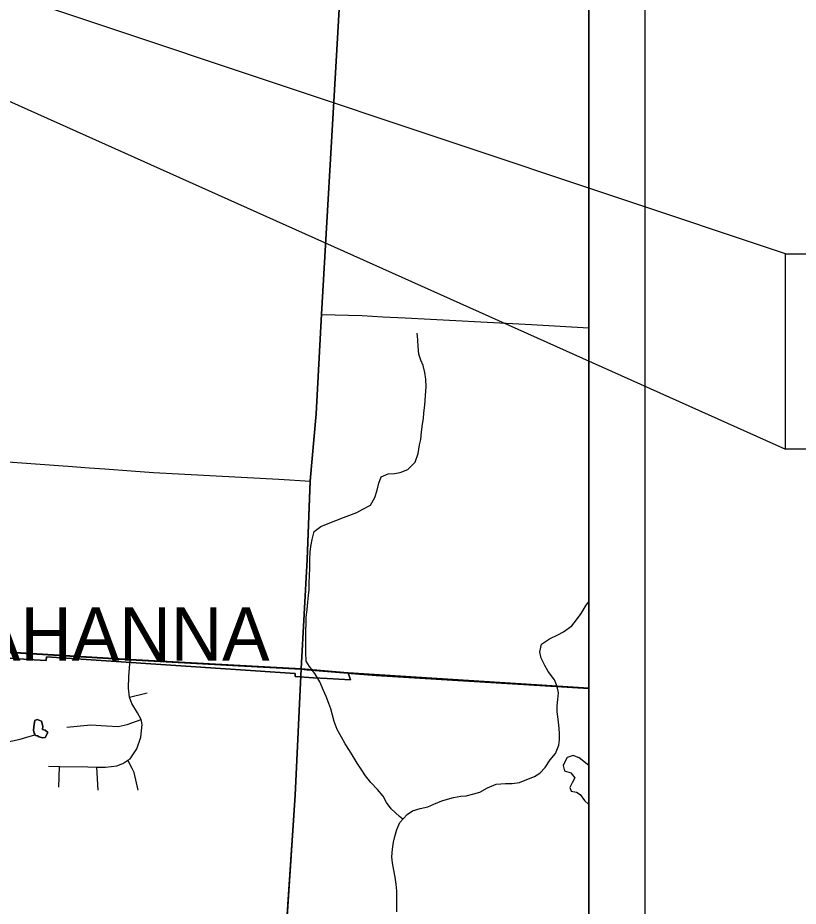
# Model space of a CAD drawing. Extents: x 0 to 34, y 0 to 22.
# Drawn here: x 7.884 to 9.273, y 15.681 to 17.262 of the extents above; entities that cross this region are included whole.
import ezdxf

# ---------------------------------------------------------------- set-up
doc = ezdxf.new("R2010")
doc.units = 0
for name, color, linetype in [('GM_X_City_Street', 7, 'Continuous'), ('GM_X_Corporation', 7, 'Continuous'), ('GM_X_Corporation_Text', 7, 'Continuous'), ('GM_X_County_Road', 7, 'Continuous'), ('GM_X_Minor_Lake', 7, 'Continuous'), ('GM_X_Minor_River', 7, 'Continuous'), ('GM_X_Township_Road', 7, 'Continuous'), ('SH_Data', 7, 'Continuous'), ('SH_Text', 7, 'Continuous')]:
    doc.layers.add(name, color=color, linetype=linetype)

msp = doc.modelspace()

# ---------------------------------------------------------------- linework, layer by layer
at = {"layer": 'GM_X_City_Street'}
for p, q in [((8.3886, 16.1027), (8.3913, 16.1519)), ((8.3881, 16.0927), (8.3886, 16.1027)), ((8.0827, 16.0532), (8.1145, 16.0607)), ((7.957, 15.8928), (7.9587, 15.9299)), ((8.027, 15.8876), (8.025, 15.9288))]:
    msp.add_line(p, q, dxfattribs=at)
for points in [[(8.3913, 16.1519), (8.3994, 16.2974), (8.4048, 16.4377), (8.4153, 16.557), (8.4248, 16.7338), (8.4513, 17.1946), (8.4576, 17.2978)], [(7.9386, 15.9301), (7.9587, 15.9299), (8.0091, 15.9292), (8.025, 15.9288), (8.0405, 15.9284), (8.0603, 15.9311), (8.0709, 15.9351), (8.0799, 15.9408), (8.0839, 15.9433), (8.096, 15.9609), (8.1031, 15.982), (8.1054, 16.0047), (8.1036, 16.0132), (8.0972, 16.0255), (8.0872, 16.0419), (8.0827, 16.0532), (8.0812, 16.0693), (8.0817, 16.0896), (8.0843, 16.1197)], [(8.3661, 15.702), (8.3777, 15.8782), (8.3881, 16.0927)], [(7.9715, 15.9998), (8.0144, 16.0037), (8.0419, 16.0021), (8.063, 16.001), (8.079, 16.0042), (8.1036, 16.0132)], [(8.0983, 15.8874), (8.0912, 15.9193), (8.0875, 15.9262), (8.0799, 15.9408)], [(8.3274, 15.0917), (8.3363, 15.2416), (8.3407, 15.3098), (8.3456, 15.3931), (8.3487, 15.4386), (8.3661, 15.702)]]:
    msp.add_lwpolyline(points, dxfattribs=at)
at = {"layer": 'GM_X_Corporation'}
for points in [[(7.7846, 16.1278), (7.9135, 16.1195), (7.9345, 16.1183), (7.9352, 16.125), (8.3778, 16.0954), (8.3778, 16.0901), (8.4106, 16.0876), (8.4349, 16.0862), (8.4761, 16.084), (8.4755, 16.0857), (8.4723, 16.0965), (8.9, 16.0691), (8.9, 20.2026)], [(8.9, 14.5345), (8.9, 16.0691), (8.4723, 16.0965), (8.4755, 16.0857), (8.4761, 16.084), (8.4349, 16.0862), (8.4106, 16.0876), (8.3778, 16.0901), (8.3778, 16.0954), (7.9352, 16.125), (7.9345, 16.1183), (7.9135, 16.1195), (7.7846, 16.1278)]]:
    msp.add_lwpolyline(points, dxfattribs=at)
at = {"layer": 'GM_X_County_Road'}
for p, q in [((7.9736, 16.4639), (8.0112, 16.4611)), ((8.0112, 16.4611), (8.0393, 16.4591)), ((8.0393, 16.4591), (8.0862, 16.4557)), ((8.3486, 16.4408), (8.4048, 16.4377)), ((8.277, 16.1089), (8.3886, 16.1027)), ((8.3886, 16.1027), (8.3985, 16.1019))]:
    msp.add_line(p, q, dxfattribs=at)
for points in [[(8.9, 16.069), (8.9, 20.9), (8.6772, 20.9), (8.636, 20.2294), (8.6104, 19.8358), (8.5745, 19.2215), (8.5742, 19.2159), (8.5739, 19.2101), (8.5602, 18.986), (8.5517, 18.8459), (8.5463, 18.6832), (8.4933, 17.8764), (8.4924, 17.8634), (8.4834, 17.726), (8.4574, 17.2984), (8.4511, 17.1951), (8.4246, 16.7343), (8.4151, 16.5575), (8.4046, 16.4383), (8.3992, 16.2979), (8.3884, 16.1033), (8.4715, 16.0965), (8.5217, 16.0919)], [(8.2619, 14.1), (8.9, 14.1), (8.9, 16.069), (8.5217, 16.0919), (8.4715, 16.0965), (8.3884, 16.1033), (8.3775, 15.8788), (8.3484, 15.4392), (8.3454, 15.3937), (8.3405, 15.3103), (8.3361, 15.2422), (8.3201, 14.9732), (8.3174, 14.9318), (8.3168, 14.9071), (8.3128, 14.8581), (8.3108, 14.8316), (8.3052, 14.7479), (8.278, 14.3415), (8.2717, 14.2404), (8.2673, 14.1742), (8.2622, 14.1033)]]:
    msp.add_lwpolyline(points, close=True, dxfattribs=at)
for points in [[(7.7224, 16.142), (8.0841, 16.1202), (8.3884, 16.1033), (8.3992, 16.2979), (8.4046, 16.4383), (8.4151, 16.5575), (8.4246, 16.7343), (8.4511, 17.1951), (8.4574, 17.2984)], [(7.1398, 16.5146), (7.2185, 16.5115), (7.2543, 16.5089), (7.3142, 16.505), (7.3662, 16.5009), (7.5077, 16.4921), (7.6179, 16.486), (7.7357, 16.4811), (7.9652, 16.4645), (7.9736, 16.4639)], [(8.0862, 16.4557), (8.1257, 16.4528), (8.3486, 16.4408)], [(6.3948, 16.2385), (6.5847, 16.222), (6.9777, 16.1936), (7.1915, 16.1769), (7.4187, 16.1623), (7.531, 16.1545), (7.5902, 16.1505), (7.7226, 16.1415), (8.0843, 16.1197), (8.277, 16.1089)], [(3.5033, 14.1), (8.2619, 14.1), (8.2622, 14.1033), (8.2673, 14.1742), (8.2717, 14.2404), (8.278, 14.3415), (8.3052, 14.7479), (8.3108, 14.8316), (8.3128, 14.8581), (8.3168, 14.9071), (8.3174, 14.9318), (8.3201, 14.9732), (8.3361, 15.2422), (8.3405, 15.3103), (8.3454, 15.3937), (8.3484, 15.4392), (8.3775, 15.8788), (8.3884, 16.1033), (8.0841, 16.1202), (7.7224, 16.142)], [(8.3985, 16.1019), (8.4717, 16.096), (8.4776, 16.0954)], [(8.4776, 16.0954), (8.5219, 16.0914), (8.9, 16.0685)]]:
    msp.add_lwpolyline(points, dxfattribs=at)
at = {"layer": 'GM_X_Minor_Lake'}
for points in [[(7.9191, 15.984), (7.9225, 15.9825), (7.9282, 15.9805), (7.9328, 15.9816), (7.9374, 15.99), (7.9329, 15.9945), (7.9279, 15.9953), (7.9287, 16.0014), (7.9261, 16.0105), (7.9186, 16.0136), (7.9144, 16.0117), (7.9136, 16.0053), (7.912, 15.9944)], [(7.912, 15.9943), (7.9136, 16.0053), (7.9144, 16.0117), (7.9186, 16.0136), (7.9261, 16.0105), (7.9287, 16.0014), (7.9279, 15.9953), (7.9329, 15.9945), (7.9374, 15.99), (7.9328, 15.9816), (7.9282, 15.9805), (7.9225, 15.9825), (7.9191, 15.984)], [(7.7947, 15.9617), (7.8306, 15.9659), (7.8428, 15.9708), (7.8526, 15.9719), (7.8629, 15.9729), (7.875, 15.9751), (7.8887, 15.9785), (7.9001, 15.9822), (7.9148, 15.9861)], [(7.912, 15.9944), (7.9136, 15.989), (7.9144, 15.9872), (7.9149, 15.9859), (7.9159, 15.9851), (7.9191, 15.984)], [(7.9191, 15.984), (7.9159, 15.9851), (7.9149, 15.9859), (7.9144, 15.9872), (7.9136, 15.989), (7.912, 15.9944)], [(8.9, 15.9316), (8.8833, 15.9453), (8.8723, 15.9495), (8.8616, 15.9458), (8.8582, 15.939), (8.8547, 15.9314), (8.8569, 15.9223), (8.8683, 15.9184), (8.8754, 15.9093), (8.8705, 15.9009), (8.8662, 15.8926), (8.8688, 15.8858), (8.8783, 15.8842), (8.8851, 15.88), (8.8927, 15.8693), (8.9, 15.8624)]]:
    msp.add_lwpolyline(points, dxfattribs=at)
at = {"layer": 'GM_X_Minor_River'}
for points in [[(8.5694, 15.8362), (8.5634, 15.8409), (8.5487, 15.8546), (8.5404, 15.8657), (8.5344, 15.8767), (8.5243, 15.8889), (8.5126, 15.9012), (8.5028, 15.913), (8.4949, 15.9252), (8.4881, 15.9355), (8.481, 15.9473), (8.4742, 15.9583), (8.4667, 15.9701), (8.4599, 15.9819), (8.4524, 15.9953), (8.4472, 16.0097), (8.4439, 16.0211), (8.4409, 16.0322), (8.4376, 16.042), (8.4331, 16.0542), (8.4282, 16.0652), (8.4219, 16.0801), (8.4125, 16.0953), (8.4031, 16.1079), (8.3974, 16.1174), (8.3968, 16.1326), (8.3968, 16.1448), (8.3966, 16.1596), (8.3966, 16.1702), (8.3971, 16.1846), (8.3975, 16.1949), (8.3988, 16.2089), (8.4, 16.2222), (8.4016, 16.2339), (8.4024, 16.2438), (8.4029, 16.2578), (8.4033, 16.2673), (8.4038, 16.2837), (8.4039, 16.2981), (8.4043, 16.311), (8.4056, 16.3212), (8.4079, 16.3337), (8.4118, 16.3481), (8.4236, 16.3568), (8.4396, 16.3635), (8.4503, 16.3676), (8.4636, 16.3725), (8.4735, 16.3762), (8.4872, 16.3815), (8.4982, 16.3875), (8.5115, 16.395), (8.5192, 16.4086), (8.5235, 16.4215), (8.5266, 16.434), (8.5305, 16.4454), (8.543, 16.4502), (8.5544, 16.4513), (8.5647, 16.4531), (8.578, 16.458), (8.591, 16.4712), (8.5968, 16.4864), (8.5988, 16.5019), (8.6011, 16.5118), (8.6027, 16.525), (8.6043, 16.5391), (8.6059, 16.5489), (8.6067, 16.5588), (8.6083, 16.5725), (8.6099, 16.5899), (8.6108, 16.6055), (8.6105, 16.6187), (8.6087, 16.6309), (8.6054, 16.6435), (8.6016, 16.653), (8.5979, 16.6632), (8.5965, 16.6769), (8.5958, 16.6887), (8.5947, 16.7005)], [(8.5585, 15.6709), (8.5587, 15.6978), (8.5584, 15.7085), (8.5573, 15.7202), (8.5555, 15.7328), (8.5533, 15.7453), (8.5508, 15.7582), (8.5497, 15.7689), (8.5509, 15.7825), (8.5529, 15.795), (8.5552, 15.8053), (8.5587, 15.8178), (8.5637, 15.8303), (8.5771, 15.8442), (8.5866, 15.8506), (8.5999, 15.8547), (8.6136, 15.8577), (8.6247, 15.8625), (8.6387, 15.8685), (8.6486, 15.8715), (8.6593, 15.8745), (8.6722, 15.8771), (8.6821, 15.8778), (8.6958, 15.8811), (8.706, 15.8841), (8.7201, 15.892), (8.7353, 15.8983), (8.7517, 15.8994), (8.7638, 15.8997), (8.7767, 15.9015), (8.7897, 15.9064), (8.8034, 15.912), (8.8129, 15.918), (8.8224, 15.9282), (8.8316, 15.9418), (8.8408, 15.9531), (8.847, 15.9675), (8.8482, 15.9774), (8.8482, 15.988), (8.8475, 15.9982), (8.8457, 16.0138), (8.8439, 16.0267), (8.8436, 16.0374), (8.8448, 16.0487), (8.8464, 16.0609), (8.8438, 16.0719), (8.839, 16.0841), (8.8281, 16.0989), (8.8217, 16.1092), (8.8157, 16.1226), (8.8131, 16.1336), (8.8162, 16.1472), (8.83, 16.1566), (8.8448, 16.1641), (8.8551, 16.1694), (8.87, 16.1803), (8.8784, 16.1905), (8.8864, 16.2018), (8.8956, 16.217), (8.9, 16.2228)]]:
    msp.add_lwpolyline(points, dxfattribs=at)
at = {"layer": 'GM_X_Township_Road'}
for points in [[(8.4248, 16.7338), (8.4969, 16.7319), (8.5337, 16.73)], [(8.5337, 16.73), (8.5734, 16.7278), (8.798, 16.7159), (8.9, 16.7102)]]:
    msp.add_lwpolyline(points, dxfattribs=at)
at = {"layer": 'SH_Data'}
for p, q in [((9, 21), (9, 14)), ((8.9, 20.9), (8.9, 14.1))]:
    msp.add_line(p, q, dxfattribs=at)
at = {"layer": 'SH_Text'}
for points in [[(9.25, 16.8419), (6.2096, 17.858), (9.25, 16.4941)], [(9.25, 16.8419), (11.4267, 16.8419), (11.4267, 16.4941), (9.25, 16.4941)]]:
    msp.add_lwpolyline(points, close=True, dxfattribs=at)

# ---------------------------------------------------------------- texts
at = {"layer": 'GM_X_Corporation_Text'}
msp.add_text('GAHANNA', height=0.0947, rotation=0, dxfattribs=at).set_placement((7.7059, 16.1181))

doc.saveas('drawing.dxf')
